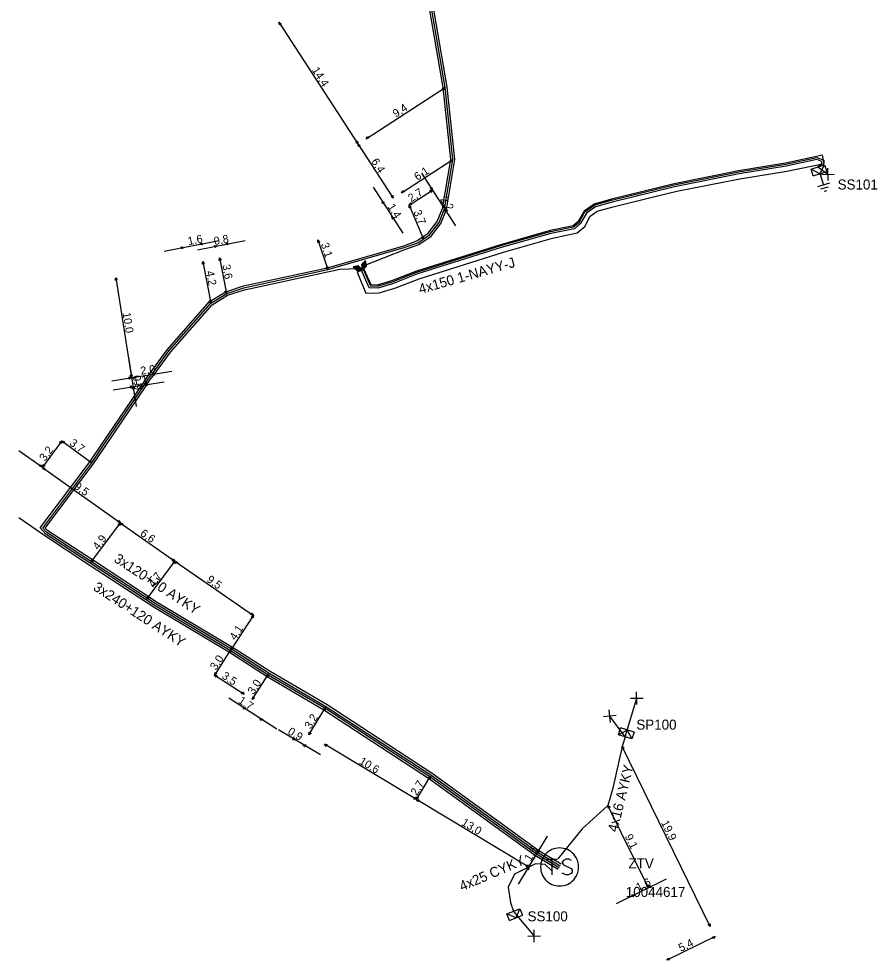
# Model space of a CAD drawing. Extents: x -761250 to -761165, y -1152671 to -1152488.
# Drawn here: x -761250 to -761164.7, y -1152670.8 to -1152577.3 of the extents above; entities that cross this region are included whole.
import ezdxf

# ---------------------------------------------------------------- set-up
doc = ezdxf.new("R2010")
doc.units = 0
for name, color, linetype in [('Vrstva 15', 7, 'Continuous'), ('Vrstva 19', 7, 'Continuous'), ('Vrstva 20', 7, 'Continuous'), ('Vrstva 25', 7, 'Continuous'), ('Vrstva 26', 7, 'Continuous'), ('Vrstva 27', 7, 'Continuous'), ('Vrstva 31', 7, 'Continuous'), ('Vrstva 33', 7, 'Continuous'), ('Vrstva 34', 7, 'Continuous'), ('Vrstva 40', 7, 'Continuous'), ('Vrstva 5', 7, 'Continuous'), ('Vrstva 59', 7, 'Continuous'), ('Vrstva 6', 7, 'Continuous')]:
    doc.layers.add(name, color=color, linetype=linetype)

msp = doc.modelspace()

# ---------------------------------------------------------------- linework, layer by layer
at = {"layer": 'Vrstva 15'}
for points in [[(-761170.408, -1152592.611), (-761170.043, -1152593.806)], [(-761169.445, -1152593.623), (-761170.64, -1152593.989)], [(-761169.585, -1152593.99), (-761170.338, -1152594.22)], [(-761169.86, -1152594.404), (-761169.982, -1152594.441)], [(-761169.733, -1152594.365), (-761169.86, -1152594.404)]]:
    msp.add_lwpolyline(points, dxfattribs=at)
at = {"layer": 'Vrstva 19'}
for points in [[(-761215.461, -1152601.858), (-761215.546, -1152601.304), (-761215.937, -1152601.703), (-761215.855, -1152602.255), (-761215.461, -1152601.858)], [(-761216.388, -1152602.309), (-761215.834, -1152602.224), (-761216.233, -1152601.833), (-761216.785, -1152601.915), (-761216.388, -1152602.309)], [(-761215.959, -1152602.187), (-761216.253, -1152601.893), (-761216.654, -1152601.957), (-761216.368, -1152602.249), (-761215.959, -1152602.187)], [(-761216.079, -1152602.148), (-761216.272, -1152601.953), (-761216.551, -1152601.995), (-761216.349, -1152602.189), (-761216.079, -1152602.148)], [(-761216.195, -1152602.111), (-761216.291, -1152602.013), (-761216.434, -1152602.033), (-761216.329, -1152602.129), (-761216.195, -1152602.111)], [(-761215.583, -1152601.429), (-761215.877, -1152601.723), (-761215.813, -1152602.124), (-761215.521, -1152601.838), (-761215.583, -1152601.429)], [(-761215.622, -1152601.549), (-761215.817, -1152601.742), (-761215.775, -1152602.021), (-761215.581, -1152601.819), (-761215.622, -1152601.549)], [(-761215.659, -1152601.665), (-761215.757, -1152601.761), (-761215.737, -1152601.904), (-761215.641, -1152601.799), (-761215.659, -1152601.665)]]:
    msp.add_lwpolyline(points, dxfattribs=at)
at = {"layer": 'Vrstva 20'}
msp.add_lwpolyline([(-761169.99, -1152591.64), (-761170.16, -1152590.84), (-761173.81, -1152591.63), (-761178.49, -1152592.37), (-761184.9, -1152593.67), (-761191.12, -1152595.2), (-761192.83, -1152595.68), (-761193.84, -1152596.38), (-761194.42, -1152597.43), (-761194.93, -1152597.86), (-761197.21, -1152598.31), (-761202.15, -1152599.72), (-761210.5, -1152602.34), (-761212.96, -1152603.32), (-761214.38, -1152603.74), (-761214.99, -1152603.72), (-761215.68, -1152602.17), (-761216.37, -1152602.45), (-761215.52, -1152604.52), (-761214.2, -1152604.51), (-761212.63, -1152604.04), (-761210.22, -1152603.1), (-761201.83, -1152600.46), (-761196.97, -1152599.06), (-761194.53, -1152598.55), (-761193.77, -1152597.92), (-761193.24, -1152596.88), (-761192.54, -1152596.39), (-761190.94, -1152595.95), (-761186.66, -1152594.91), (-761184.63, -1152594.41), (-761178.36, -1152593.17), (-761173.69, -1152592.43)], close=True, dxfattribs=at)
at = {"layer": 'Vrstva 25'}
for points in [[(-761194.377, -1152661.531), (-761194.388, -1152661.334), (-761194.419, -1152661.138), (-761194.47, -1152660.947), (-761194.542, -1152660.763), (-761194.631, -1152660.587), (-761194.739, -1152660.421), (-761194.863, -1152660.267), (-761195.003, -1152660.127), (-761195.157, -1152660.003), (-761195.323, -1152659.895), (-761195.499, -1152659.805), (-761195.683, -1152659.734), (-761196.07, -1152659.652), (-761196.07, -1152659.652), (-761196.267, -1152659.641), (-761196.465, -1152659.652), (-761196.661, -1152659.683), (-761196.851, -1152659.734), (-761197.037, -1152659.805), (-761197.212, -1152659.895), (-761197.378, -1152660.003), (-761197.532, -1152660.127), (-761197.672, -1152660.267), (-761197.796, -1152660.421), (-761197.904, -1152660.587), (-761197.994, -1152660.763), (-761198.065, -1152660.947), (-761198.116, -1152661.138), (-761198.147, -1152661.334), (-761198.158, -1152661.531), (-761198.147, -1152661.729), (-761198.116, -1152661.925), (-761198.065, -1152662.115), (-761197.994, -1152662.3), (-761197.904, -1152662.476), (-761197.796, -1152662.642), (-761197.671, -1152662.796), (-761197.532, -1152662.935), (-761197.378, -1152663.06), (-761197.212, -1152663.168), (-761197.036, -1152663.258), (-761196.851, -1152663.329), (-761196.661, -1152663.38), (-761196.465, -1152663.411), (-761196.267, -1152663.422), (-761196.07, -1152663.411), (-761195.875, -1152663.38), (-761195.683, -1152663.329), (-761195.499, -1152663.258), (-761195.323, -1152663.168), (-761195.157, -1152663.06), (-761195.003, -1152662.935), (-761194.863, -1152662.796), (-761194.739, -1152662.642), (-761194.631, -1152662.476), (-761194.542, -1152662.3), (-761194.47, -1152662.115), (-761194.419, -1152661.925), (-761194.388, -1152661.729), (-761194.377, -1152661.531)], [(-761197.529, -1152660.748), (-761196.521, -1152660.748)], [(-761197.025, -1152660.748), (-761197.025, -1152662.322)], [(-761195.072, -1152660.874), (-761195.324, -1152660.748), (-761195.639, -1152660.748), (-761195.891, -1152660.874), (-761196.017, -1152661.062), (-761196.017, -1152661.126), (-761195.891, -1152661.314), (-761195.135, -1152661.692), (-761195.009, -1152661.85), (-761195.009, -1152662.008), (-761195.135, -1152662.196), (-761195.387, -1152662.322), (-761195.639, -1152662.322), (-761195.765, -1152662.26), (-761196.017, -1152662.134)]]:
    msp.add_lwpolyline(points, dxfattribs=at)
at = {"layer": 'Vrstva 31'}
for points in [[(-761171.068, -1152592.876), (-761171.273, -1152592.206), (-761169.934, -1152591.797), (-761169.729, -1152592.466)], [(-761170.398, -1152592.671), (-761169.934, -1152591.797)], [(-761170.398, -1152592.671), (-761171.273, -1152592.206)], [(-761171.068, -1152592.876), (-761169.729, -1152592.466)], [(-761188.873, -1152648.136), (-761189.078, -1152648.805), (-761190.417, -1152648.396), (-761190.212, -1152647.726)], [(-761189.542, -1152647.931), (-761190.417, -1152648.396)], [(-761188.873, -1152648.136), (-761190.212, -1152647.726)], [(-761189.542, -1152647.931), (-761189.078, -1152648.805)], [(-761201.239, -1152666.853), (-761201.502, -1152666.204), (-761200.203, -1152665.679), (-761199.941, -1152666.328)], [(-761200.59, -1152666.59), (-761200.203, -1152665.679)], [(-761200.59, -1152666.59), (-761201.502, -1152666.204)], [(-761201.239, -1152666.853), (-761199.941, -1152666.328)]]:
    msp.add_lwpolyline(points, dxfattribs=at)
at = {"layer": 'Vrstva 34'}
for points in [[(-761170.235, -1152592.741), (-761168.985, -1152592.719)], [(-761169.599, -1152593.355), (-761169.621, -1152592.105)], [(-761188.589, -1152645.395), (-761188.611, -1152644.145)], [(-761189.225, -1152644.781), (-761187.975, -1152644.759)], [(-761191.205, -1152647.182), (-761191.335, -1152645.939)], [(-761190.648, -1152646.495), (-761191.892, -1152646.626)], [(-761199.415, -1152668.401), (-761198.165, -1152668.379)], [(-761198.779, -1152669.015), (-761198.801, -1152667.765)]]:
    msp.add_lwpolyline(points, dxfattribs=at)
at = {"layer": 'Vrstva 40'}
for points in [[(-761224.152, -1152577.627), (-761223.926, -1152577.775), (-761224.099, -1152577.892)], [(-761207.648, -1152584.088), (-761207.796, -1152584.314), (-761207.913, -1152584.141)], [(-761215.492, -1152589.191), (-761215.344, -1152588.966), (-761215.228, -1152589.139)], [(-761216.299, -1152589.712), (-761216.524, -1152589.565), (-761216.351, -1152589.448)], [(-761216.301, -1152589.708), (-761216.075, -1152589.855), (-761216.249, -1152589.972)], [(-761206.888, -1152591.258), (-761207.036, -1152591.484), (-761207.153, -1152591.311)], [(-761211.992, -1152594.571), (-761211.845, -1152594.346), (-761211.728, -1152594.519)], [(-761208.908, -1152594.298), (-761209.056, -1152594.524), (-761209.173, -1152594.351)], [(-761208.909, -1152594.302), (-761209.134, -1152594.155), (-761208.961, -1152594.038)], [(-761213.709, -1152595.702), (-761213.935, -1152595.554), (-761213.761, -1152595.437)], [(-761212.789, -1152595.102), (-761213.015, -1152594.954), (-761212.841, -1152594.838)], [(-761211.202, -1152595.791), (-761211.055, -1152595.565), (-761210.938, -1152595.739)], [(-761211.221, -1152595.798), (-761211.027, -1152595.986), (-761211.22, -1152596.067)], [(-761207.701, -1152596.168), (-761207.476, -1152596.315), (-761207.649, -1152596.432)], [(-761212.921, -1152596.907), (-761212.696, -1152597.055), (-761212.869, -1152597.172)], [(-761220.281, -1152599.227), (-761220.101, -1152599.428), (-761220.299, -1152599.496)], [(-761209.8, -1152599.183), (-761209.993, -1152598.995), (-761209.801, -1152598.913)], [(-761233.598, -1152599.99), (-761233.819, -1152600.144), (-761233.863, -1152599.939)], [(-761232.063, -1152599.691), (-761231.841, -1152599.537), (-761231.798, -1152599.741)], [(-761230.278, -1152599.85), (-761230.499, -1152600.004), (-761230.542, -1152599.799)], [(-761229.482, -1152599.69), (-761229.261, -1152599.536), (-761229.218, -1152599.74)], [(-761230.051, -1152601.037), (-761229.9, -1152601.261), (-761230.106, -1152601.301)], [(-761231.73, -1152601.378), (-761231.576, -1152601.599), (-761231.78, -1152601.643)], [(-761219.289, -1152602.203), (-761219.469, -1152602.002), (-761219.271, -1152601.934)], [(-761240.36, -1152602.997), (-761240.218, -1152603.227), (-761240.424, -1152603.259)], [(-761229.38, -1152604.583), (-761229.53, -1152604.358), (-761229.325, -1152604.319)], [(-761230.919, -1152605.522), (-761231.073, -1152605.301), (-761230.869, -1152605.258)], [(-761236.783, -1152612.601), (-761236.553, -1152612.458), (-761236.521, -1152612.665)], [(-761238.788, -1152612.92), (-761239.017, -1152613.062), (-761239.05, -1152612.856)], [(-761238.79, -1152612.922), (-761238.932, -1152612.693), (-761238.726, -1152612.661)], [(-761238.79, -1152612.923), (-761238.932, -1152612.693), (-761238.725, -1152612.661)], [(-761238.647, -1152613.819), (-761238.877, -1152613.961), (-761238.909, -1152613.755)], [(-761238.65, -1152613.817), (-761238.508, -1152614.047), (-761238.715, -1152614.079)], [(-761237.523, -1152613.641), (-761237.293, -1152613.499), (-761237.261, -1152613.705)], [(-761245.718, -1152619.208), (-761245.78, -1152619.471), (-761245.949, -1152619.348)], [(-761245.722, -1152619.208), (-761245.459, -1152619.27), (-761245.582, -1152619.439)], [(-761247.638, -1152621.821), (-761247.901, -1152621.764), (-761247.781, -1152621.593)], [(-761247.662, -1152621.849), (-761247.399, -1152621.906), (-761247.519, -1152622.077)], [(-761247.642, -1152621.822), (-761247.58, -1152621.559), (-761247.411, -1152621.682)], [(-761242.758, -1152621.391), (-761243.021, -1152621.33), (-761242.898, -1152621.161)], [(-761239.908, -1152627.342), (-761240.172, -1152627.285), (-761240.052, -1152627.114)], [(-761239.908, -1152627.338), (-761239.97, -1152627.601), (-761240.139, -1152627.478)], [(-761239.932, -1152627.358), (-761239.668, -1152627.411), (-761239.785, -1152627.584)], [(-761242.831, -1152631.302), (-761242.77, -1152631.04), (-761242.601, -1152631.163)], [(-761234.488, -1152631.161), (-761234.753, -1152631.109), (-761234.636, -1152630.936)], [(-761234.479, -1152631.138), (-761234.54, -1152631.4), (-761234.709, -1152631.277)], [(-761234.492, -1152631.159), (-761234.228, -1152631.211), (-761234.345, -1152631.384)], [(-761237.282, -1152634.932), (-761237.22, -1152634.67), (-761237.051, -1152634.792)], [(-761226.688, -1152636.552), (-761226.953, -1152636.499), (-761226.836, -1152636.326)], [(-761226.668, -1152636.518), (-761226.716, -1152636.783), (-761226.891, -1152636.67)], [(-761228.919, -1152639.978), (-761228.967, -1152640.244), (-761229.142, -1152640.13)], [(-761228.922, -1152639.982), (-761228.874, -1152639.717), (-761228.699, -1152639.831)], [(-761230.542, -1152642.472), (-761230.494, -1152642.207), (-761230.318, -1152642.32)], [(-761230.542, -1152642.468), (-761230.277, -1152642.516), (-761230.39, -1152642.691)], [(-761225.179, -1152642.388), (-761225.227, -1152642.653), (-761225.402, -1152642.539)], [(-761227.618, -1152644.371), (-761227.884, -1152644.324), (-761227.77, -1152644.148)], [(-761226.812, -1152644.902), (-761226.764, -1152644.637), (-761226.589, -1152644.75)], [(-761227.438, -1152645.872), (-761227.704, -1152645.824), (-761227.59, -1152645.649)], [(-761219.528, -1152645.688), (-761219.562, -1152645.956), (-761219.743, -1152645.851)], [(-761226.052, -1152646.769), (-761225.786, -1152646.817), (-761225.9, -1152646.992)], [(-761222.498, -1152648.932), (-761222.765, -1152648.898), (-761222.661, -1152648.717)], [(-761221.172, -1152648.422), (-761221.138, -1152648.155), (-761220.957, -1152648.259)], [(-761221.752, -1152649.378), (-761221.484, -1152649.412), (-761221.589, -1152649.593)], [(-761219.622, -1152649.349), (-761219.355, -1152649.382), (-761219.459, -1152649.564)], [(-761190.051, -1152649.548), (-761189.845, -1152649.722), (-761190.031, -1152649.817)], [(-761209.108, -1152652.507), (-761209.142, -1152652.775), (-761209.323, -1152652.671)], [(-761210.498, -1152654.822), (-761210.766, -1152654.788), (-761210.661, -1152654.607)], [(-761210.502, -1152654.822), (-761210.468, -1152654.554), (-761210.287, -1152654.659)], [(-761210.502, -1152654.819), (-761210.235, -1152654.852), (-761210.339, -1152655.033)], [(-761191.461, -1152655.417), (-761191.255, -1152655.591), (-761191.441, -1152655.686)], [(-761198.501, -1152660.192), (-761198.467, -1152659.924), (-761198.286, -1152660.029)], [(-761199.308, -1152661.541), (-761199.575, -1152661.508), (-761199.471, -1152661.327)], [(-761199.309, -1152661.538), (-761199.343, -1152661.805), (-761199.524, -1152661.701)], [(-761187.429, -1152663.592), (-761187.635, -1152663.418), (-761187.448, -1152663.323)], [(-761187.432, -1152663.591), (-761187.258, -1152663.385), (-761187.163, -1152663.571)], [(-761188.827, -1152664.279), (-761189.002, -1152664.485), (-761189.096, -1152664.299)], [(-761181.299, -1152667.442), (-761181.505, -1152667.268), (-761181.319, -1152667.173)], [(-761180.808, -1152668.439), (-761180.982, -1152668.645), (-761181.077, -1152668.459)], [(-761185.622, -1152670.791), (-761185.448, -1152670.585), (-761185.353, -1152670.771)]]:
    msp.add_lwpolyline(points, close=True, dxfattribs=at)
for points in [[(-761224.15, -1152577.63), (-761216.3, -1152589.71)], [(-761215.49, -1152589.19), (-761207.65, -1152584.09)], [(-761216.3, -1152589.71), (-761212.79, -1152595.1)], [(-761211.99, -1152594.57), (-761206.89, -1152591.26)], [(-761210, -1152592.63), (-761206.61, -1152597.85)], [(-761214.8, -1152594.02), (-761211.83, -1152598.59)], [(-761211.2, -1152595.79), (-761208.91, -1152594.3)], [(-761211.22, -1152595.8), (-761209.8, -1152599.18)], [(-761235.56, -1152600.37), (-761230.1, -1152599.3)], [(-761232.24, -1152600.23), (-761227.51, -1152599.31)], [(-761220.28, -1152599.23), (-761219.29, -1152602.2)], [(-761230.05, -1152601.04), (-761229.38, -1152604.58)], [(-761231.73, -1152601.38), (-761230.92, -1152605.52)], [(-761240.36, -1152603), (-761238.79, -1152612.92)], [(-761239.11, -1152610.94), (-761238.34, -1152615.8)], [(-761240.77, -1152613.23), (-761234.81, -1152612.29)], [(-761240.63, -1152614.13), (-761235.55, -1152613.33)], [(-761245.72, -1152619.21), (-761247.64, -1152621.82)], [(-761245.72, -1152619.21), (-761242.76, -1152621.39)], [(-761250, -1152620.15), (-761247.64, -1152621.82)], [(-761247.66, -1152621.85), (-761239.91, -1152627.34)], [(-761242.83, -1152631.3), (-761239.91, -1152627.34)], [(-761239.93, -1152627.36), (-761234.49, -1152631.16)], [(-761237.28, -1152634.93), (-761234.48, -1152631.14)], [(-761234.49, -1152631.16), (-761226.69, -1152636.55)], [(-761226.67, -1152636.52), (-761228.92, -1152639.98)], [(-761230.54, -1152642.47), (-761228.92, -1152639.98)], [(-761226.81, -1152644.9), (-761225.18, -1152642.39)], [(-761230.54, -1152642.47), (-761227.62, -1152644.37)], [(-761224.38, -1152647.86), (-761229.12, -1152644.78)], [(-761221.17, -1152648.42), (-761219.53, -1152645.69)], [(-761220.03, -1152650.41), (-761224.21, -1152647.9)], [(-761210.5, -1152654.82), (-761219.62, -1152649.35)], [(-761181.3, -1152667.44), (-761190.05, -1152649.55)], [(-761210.5, -1152654.82), (-761209.11, -1152652.51)], [(-761199.31, -1152661.54), (-761210.5, -1152654.82)], [(-761187.43, -1152663.59), (-761191.46, -1152655.42)], [(-761200.34, -1152663.25), (-761197.47, -1152658.48)], [(-761190.62, -1152665.16), (-761185.64, -1152662.71)], [(-761180.81, -1152668.44), (-761185.62, -1152670.79)]]:
    msp.add_lwpolyline(points, dxfattribs=at)
at = {"layer": 'Vrstva 5'}
for points in [[(-761196.31, -1152661.62), (-761198.56, -1152660.27), (-761209.17, -1152652.59), (-761219.58, -1152645.77), (-761225.23, -1152642.48), (-761228.97, -1152640.07), (-761236.45, -1152635.59), (-761242.9, -1152631.37), (-761247.33, -1152628.48), (-761247.88, -1152627.86), (-761242.92, -1152621.27), (-761241.69, -1152619.44), (-761237.69, -1152613.53), (-761237.29, -1152612.9), (-761236.94, -1152612.48), (-761235.25, -1152610.16), (-761231.05, -1152605.37), (-761229.42, -1152604.39), (-761227.69, -1152603.82), (-761219.34, -1152602.01), (-761211.76, -1152599.82), (-761210.44, -1152599.35), (-761209.32, -1152598.58), (-761208.43, -1152597.43), (-761207.89, -1152596.12), (-761207.09, -1152591.25), (-761207.85, -1152584.12), (-761209.46, -1152574.68)], [(-761196.21, -1152661.44), (-761198.45, -1152660.11), (-761209.05, -1152652.43), (-761219.48, -1152645.61), (-761225.13, -1152642.31), (-761228.87, -1152639.9), (-761236.35, -1152635.42), (-761242.79, -1152631.21), (-761247.22, -1152628.32), (-761247.63, -1152627.87), (-761242.76, -1152621.39), (-761241.52, -1152619.55), (-761237.52, -1152613.64), (-761237.13, -1152613.02), (-761236.78, -1152612.6), (-761235.09, -1152610.28), (-761230.92, -1152605.52), (-761229.34, -1152604.57), (-761227.64, -1152604.01), (-761219.29, -1152602.2), (-761211.7, -1152600.01), (-761210.35, -1152599.53), (-761209.18, -1152598.73), (-761208.25, -1152597.53), (-761207.7, -1152596.17), (-761206.89, -1152591.26), (-761207.65, -1152584.09), (-761209.26, -1152574.64)], [(-761215.7, -1152601.78), (-761211.63, -1152600.2), (-761210.26, -1152599.71), (-761209.04, -1152598.88), (-761208.08, -1152597.63), (-761207.51, -1152596.22), (-761206.69, -1152591.27), (-761207.45, -1152584.06), (-761209.06, -1152574.6)], [(-761215.7, -1152601.78), (-761215.82, -1152602.09), (-761215.05, -1152603.82), (-761214.36, -1152603.84), (-761212.92, -1152603.42), (-761210.46, -1152602.44), (-761202.12, -1152599.81), (-761197.18, -1152598.4), (-761194.89, -1152597.96), (-761194.34, -1152597.5), (-761193.77, -1152596.45), (-761192.78, -1152595.77), (-761191.1, -1152595.29), (-761184.88, -1152593.76), (-761178.47, -1152592.47), (-761173.79, -1152591.73), (-761170.7, -1152591.06), (-761170.01, -1152591.31), (-761170.05, -1152591.87), (-761170.6, -1152592), (-761170.24, -1152591.73), (-761170.22, -1152591.45), (-761170.72, -1152591.26), (-761173.75, -1152591.93), (-761178.43, -1152592.67), (-761184.84, -1152593.96), (-761191.04, -1152595.49), (-761192.7, -1152595.95), (-761193.61, -1152596.59), (-761194.18, -1152597.62), (-761194.8, -1152598.14), (-761197.14, -1152598.6), (-761202.06, -1152600.01), (-761210.4, -1152602.62), (-761212.86, -1152603.61), (-761214.34, -1152604.04), (-761215.19, -1152604.02), (-761216, -1152602.18), (-761216.31, -1152602.07)], [(-761196.11, -1152661.27), (-761198.34, -1152659.94), (-761208.94, -1152652.26), (-761219.37, -1152645.44), (-761225.02, -1152642.13), (-761228.76, -1152639.73), (-761236.24, -1152635.25), (-761242.68, -1152631.04), (-761247.11, -1152628.15), (-761247.38, -1152627.88), (-761242.6, -1152621.51), (-761241.35, -1152619.66), (-761237.35, -1152613.75), (-761236.97, -1152613.14), (-761236.62, -1152612.72), (-761234.93, -1152610.41), (-761230.79, -1152605.68), (-761229.26, -1152604.75), (-761227.59, -1152604.2), (-761218.11, -1152602.15), (-761216.31, -1152602.07)], [(-761196.41, -1152661.79), (-761198.67, -1152660.44), (-761209.28, -1152652.76), (-761219.69, -1152645.95), (-761225.34, -1152642.65), (-761229.08, -1152640.24), (-761236.56, -1152635.75), (-761243, -1152631.54), (-761247.43, -1152628.65), (-761250, -1152626.86)], [(-761189.75, -1152648.6), (-761190.05, -1152649.55), (-761191.01, -1152653.85), (-761191.46, -1152655.42), (-761194.04, -1152657.74), (-761196.43, -1152660.74)], [(-761197.07, -1152661.89), (-761197.69, -1152661.3), (-761198.66, -1152661.23), (-761200.75, -1152662.26), (-761201.39, -1152663.53), (-761201.15, -1152665.07), (-761200.85, -1152665.94)]]:
    msp.add_lwpolyline(points, dxfattribs=at)
at = {"layer": 'Vrstva 59'}
for points in [[(-761170.6, -1152592), (-761169.61, -1152592.73)], [(-761189.75, -1152648.6), (-761188.6, -1152644.77)], [(-761189.75, -1152648.6), (-761191.27, -1152646.56)], [(-761200.85, -1152665.94), (-761198.79, -1152668.39)]]:
    msp.add_lwpolyline(points, dxfattribs=at)

# ---------------------------------------------------------------- texts
at = {"layer": 'Vrstva 26'}
msp.add_text('10044617', height=0.9943, dxfattribs=at).set_placement((-761189.69, -1152664.51))
at = {"layer": 'Vrstva 27'}
msp.add_text('ZTV', height=0.9943, dxfattribs=at).set_placement((-761189.42, -1152661.67))
at = {"layer": 'Vrstva 33'}
for s, p in [('SS101', (-761168.64, -1152594.24)), ('SP100', (-761188.64, -1152647.89)), ('SS100', (-761199.45, -1152666.93))]:
    msp.add_text(s, height=0.9943, dxfattribs=at).set_placement(p)
at = {"layer": 'Vrstva 40'}
for s, rotation, p in [('14,4', 303.02027, (-761220.92, -1152582.38)), ('9,4', 33.02033, (-761212.53, -1152587.12)), ('6,4', 303.02007, (-761215.02, -1152591.45)), ('6,1', 33.01976, (-761210.4, -1152593.39)), ('2,7', 33.01929, (-761211.01, -1152595.52)), ('1,4', 303.01981, (-761213.4, -1152595.96)), ('2,2', 303.02906, (-761208.18, -1152595.22)), ('3,7', 292.74532, (-761210.81, -1152596.46)), ('1,6', 11.06275, (-761233.13, -1152599.77)), ('0,8', 11.06162, (-761230.54, -1152599.77)), ('3,1', 288.30635, (-761220, -1152599.67)), ('3,6', 280.66879, (-761229.79, -1152601.75)), ('4,2', 281.09115, (-761231.41, -1152602.39)), ('10,0', 278.98072, (-761239.69, -1152606.5)), ('2,0', 8.96838, (-761237.85, -1152612.65)), ('0,9', 278.98259, (-761238.7, -1152612.75)), ('1,1', 8.99947, (-761238.59, -1152613.69)), ('3,7', 323.63904, (-761245.02, -1152619.57)), ('3,2', 53.61324, (-761247.4, -1152621.3)), ('9,5', 324.62269, (-761244.58, -1152623.88)), ('6,6', 325.07542, (-761238.01, -1152628.55)), ('4,9', 53.61399, (-761242.1, -1152630.1)), ('4,7', 53.61431, (-761236.6, -1152633.82)), ('9,5', 325.39316, (-761231.4, -1152633.15)), ('4,1', 56.97048, (-761228.47, -1152639.08)), ('3,0', 56.97064, (-761230.41, -1152642.05)), ('3,5', 326.97592, (-761229.9, -1152642.74)), ('3,0', 56.97699, (-761226.67, -1152644.47)), ('1,7', 326.97691, (-761228.27, -1152645.19)), ('3,2', 59.03648, (-761221, -1152647.9)), ('0,9', 329.0371, (-761223.35, -1152648.28)), ('10,6', 329.03638, (-761216.25, -1152651.23)), ('2,7', 59.03096, (-761210.45, -1152654.51)), ('13,0', 329.03642, (-761206.09, -1152657.33)), ('19,9', 296.05537, (-761186.21, -1152657.13)), ('9,1', 296.255, (-761189.81, -1152658.5)), ('1,6', 59.03624, (-761199.15, -1152661.04)), ('1,6', 26.2395, (-761188.44, -1152663.95)), ('5,4', 26.05546, (-761184.22, -1152669.98))]:
    msp.add_text(s, height=0.7954, rotation=rotation, dxfattribs=at).set_placement(p)
at = {"layer": 'Vrstva 6'}
for s, height, rotation, p in [('4x150 1-NAYY-J', 0.99428, 15.9639, (-761210.12, -1152604.63)), ('3x120+70 AYKY', 0.99429, 326.82461, (-761240.63, -1152631.15)), ('3x240+120 AYKY', 0.99429, 326.86187, (-761242.69, -1152633.97)), ('4x16 AYKY', 0.9943, 76.28985, (-761190.54, -1152658.13)), ('4x25 CYKY', 0.9943, 23.25069, (-761205.97, -1152663.96))]:
    msp.add_text(s, height=height, rotation=rotation, dxfattribs=at).set_placement(p)

doc.saveas('drawing.dxf')
